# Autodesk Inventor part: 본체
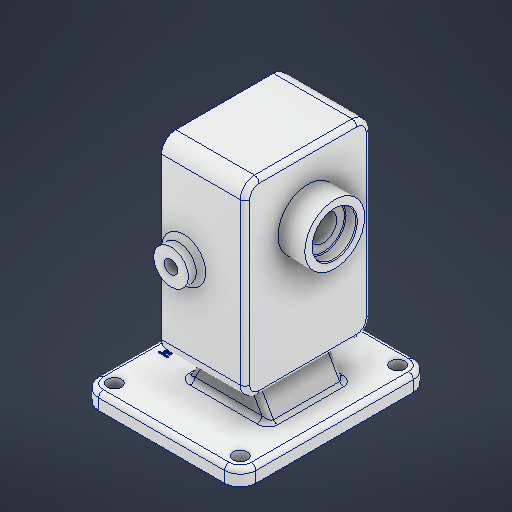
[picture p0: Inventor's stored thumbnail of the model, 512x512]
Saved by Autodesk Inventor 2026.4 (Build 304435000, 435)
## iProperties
Created: 2026-10
Part Number: 본체
Material: 알루미늄 6061
Document SubType Name: Modeling
Designer: user
Density: 2.7 g/cm^3
Appearance: 알루미늄 - 평지
Mass: 1474.42 g
Surface Area: 824.498 cm^2
Volume: 546.08 cm^3
Author: user
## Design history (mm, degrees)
sketch "스케치1"
  geometry: L1 (50, -60)-(-50, -60); L2 (-50, -60)-(-50, 60); L3 (-50, 60)-(50, 60); L4 (50, 60)-(50, -60); 1 further point
  constraints: 8 end point, 2 parallel, 1 horizontal, 1 perpendicular
  dimensions: "d0" = 100 distance of L2.end L3.end; "d1" = 120 distance of L3.end L1.start; "d2" = 60 distance from line of point (0, 0) L1; "d3" = 50 distance from line of point (0, 0) L4
extrude "돌출1" new body sketch "스케치1" distance "d4" = 10; taper "d5" = 0 deg
fillet "모깎기1" dims "d6" = 10
sketch "스케치2"
  geometry: C1 r 4.5 at (-40, 50); A1 r 10 centre (-40, 50) between (-40, 60) and (-50, 50) reference; 1 further point
  constraints: 1 centre point, 1 coincident
  dimensions: "d7" = 4.5 radius of C1
extrude "돌출2" cut sketch "스케치2" extent not by distance; stored distance "d8" = 0; taper "d9" = 0 deg
node "작업 평면1"
sketch "스케치3"
  geometry: L1 (10, 150)-(90, 150); L2 (90, 150)-(90, 30); L3 (90, 30)-(10, 30); L4 (10, 30)-(10, 150); L5 (0, 0)-(100, 0) reference; 3 further points
  constraints: 8 end point, 2 midpoint, 2 parallel, 1 horizontal, 1 perpendicular
  dimensions: "d11" = 120 distance of L3.end L1.start; "d12" = 80 distance of L1.start L1.end; "d13" = 90 distance from line of L5 point (10, 90); "d14" = 40 distance from line of point (50, 0) L4
extrude "돌출3" join sketch "스케치3" distance "d15" = 53; taper "d16" = 0 deg
sketch "스케치4"
  geometry: L1 (40, 10)-(-40, 10) reference; L2 (-20, 10)-(-3.032, 39.39); L3 (-3.032, 39.39)-(16.032, 39.39); L4 (33, 30)-(-20, 30) reference; L5 (16.032, 39.39)-(33, 10); L6 (35.5, 10)-(44.5, 10) reference; L7 (-20, 10)-(33, 10); L8 (50, 10)-(50, 0) reference; 1 further point
  constraints: 8 end point, 2 parallel, 2 point on line, 1 horizontal alignment
  dimensions: "d17" = 60 deg angle of L1 L5; "d18" = 60 deg angle of L1 L2; "d19" = 17 distance from line of L8 L5.end; "d20" = 29.38963 distance between parallel lines of L1 L3; "d21" = 53 distance of L5.end L2.start
extrude "돌출4" join sketch "스케치4" stored distance "d22" = 48; taper "d23" = 0 deg
sketch "스케치5"
  geometry: L1 (-50, 112)-(-50, 68); L2 (-74, 112)-(-74, 68); L3 (-26, 68)-(-26, 112); L4 (-90, 150)-(-90, 30) reference; L5 (-100, 10)-(0, 10) reference; A1 r 24 centre (-50, 112) between (-26, 112) and (-74, 112); A2 r 24 centre (-50, 68) between (-74, 68) and (-26, 68); 4 further points
  constraints: 8 end point, 4 point on circle, 4 tangent, 3 midpoint, 2 centre point, 1 horizontal alignment, 1 parallel, 1 vertical, 1 vertical alignment
  dimensions: "d24" = 24 radius of A2; "d25" = 44 distance of L1.start L1.end
extrude "돌출5" cut sketch "스케치5" distance "d26" = 29; taper "d27" = 0 deg
sketch "스케치6"
  geometry: C1 r 12.5 at (-50, 68); A1 r 24 centre (-50, 68) between (-74, 68) and (-26, 68) reference; 1 further point
  constraints: 1 centre point, 1 coincident
  dimensions: "d28" = 12.5 radius of C1
extrude "돌출6" cut sketch "스케치6" distance "d29" = 15; taper "d30" = 0 deg
sketch "스케치7"
  geometry: C1 r 12.5 at (-50, 112); A1 r 24 centre (-50, 112) between (-26, 112) and (-74, 112) reference; 1 further point
  constraints: 1 centre point, 1 coincident
  dimensions: "d31" = 12.5 radius of C1
extrude "돌출7" cut sketch "스케치7" distance "d32" = 15; taper "d33" = 0 deg
sketch "스케치9"
  geometry: C1 r 19 at (50, 112); A1 r 24 centre (50, 112) between (74, 112) and (26, 112) reference; 1 further point
  constraints: 1 centre point, 1 coincident
  dimensions: "d34" = 19 radius of C1
extrude "돌출8" join sketch "스케치9" distance "d35" = 17; taper "d36" = 0 deg
sketch "스케치10"
  geometry: C1 r 14 at (0, 0); A1 r 24 centre (0, 0) between (24, 0) and (-24, 0) reference; 1 further point
  constraints: 1 centre point, 1 coincident
  dimensions: "d37" = 14 radius of C1
extrude "돌출9" cut sketch "스케치10" distance "d38" = 7.3; taper "d39" = 0 deg
sketch "스케치11"
  geometry: C1 r 12.5 at (0, 0) reference; C2 r 8.5 at (0, 0); 1 further point
  constraints: 1 centre point, 1 coincident
  dimensions: "d40" = 8.5 radius of C2
extrude "돌출10" cut sketch "스케치11" extent not by distance; stored distance "d41" = 0; taper "d42" = 0 deg
sketch "스케치12"
  geometry: L1 (53, 120)-(53, 0) reference; L2 (-7, -30)-(73, -30) reference; C1 r 11 at (39, 60); 2 further points
  constraints: 1 centre point, 1 midpoint
  dimensions: "d43" = 11 radius of C1; "d44" = 14 distance of point (53, 60) C1.centre; "d45" = 90 distance from line of L2 C1.centre
extrude "돌출11" join sketch "스케치12" distance "d46" = 8; taper "d47" = 0 deg
fillet "모깎기2" dims "d48" = 3
fillet "모깎기3" dims "d49" = 9
fillet "모깎기4" dims "d50" = 3
chamfer "모따기1" distance "d51" = 1; stored, may be unused: second distance "d52" = 2, angle "d53" = 45 deg
fillet "모깎기5" dims "d54" = 0.5
chamfer "모따기2" distance "d55" = 0.7; stored, may be unused: second distance "d56" = 2, angle "d57" = 30 deg
sketch "스케치14"
  geometry: 1 further point
sketch "스케치15"
  geometry: C1 r 11 at (0, 0) reference; 2 further points
  constraints: 1 coincident
hole "구멍2" sketch "스케치15" diameter "d67" = 8; stored, may be unused: countersink angle "d73" = 82 deg, drill point angle "d75" = 0 deg; dims "d68" = 7.4, "d69" = 0.62479, "d70" = 7.985, "d71" = 3.023, "d72" = 2, "d74" = 30.9
sketch "스케치18"
  geometry: L1 (-50, 50)-(-50, -50) reference; 3 further points
  constraints: 1 horizontal alignment, 1 midpoint, 1 other
  dimensions: "d76" = 10 distance from line of L1 point (-40, 0)
feature "엠보싱1" sketch "스케치18" dims "d77" = 0.5, "d78" = 0
sketch "스케치19"
  geometry: C1 r 2.067 at (-81, 141) reference; C2 r 2.067 at (-81, 39) reference; 5 further points
  constraints: 2 coincident, 2 vertical alignment
  dimensions: "d79" = 29 distance of point (-81, 141) point (-81, 112); "d80" = 29 distance of C2.centre point (-81, 68)
hole "구멍3" sketch "스케치19" at (-81, 141), (-81, 112), (-81, 68), (-81, 39) diameter "d81" = 4.134; stored, may be unused: countersink angle "d85" = 90 deg, drill point angle "d87" = 118 deg; dims "d82" = 10, "d83" = 4, "d84" = 2, "d86" = 12
sketch "스케치20"
  geometry: 1 further point
fillet "모깎기6" dims "d88" = 3
node "솔리드1"
mirror "미러1"
mirror "미러2"
mirror "미러3"
mirror "미러5"
mirror "미러6"
feature "A9D066F2-1C7D-4E18-AEED-F7BC21143FA4" dims "d67" = 8, "d68" = 7.4, "d69" = 0.62479, "d70" = 7.985, "d71" = 3.023, "d72" = 2, "d73" = 82 deg, "d74" = 30.9, "d75" = 0
other parameters: "d10" = -17
